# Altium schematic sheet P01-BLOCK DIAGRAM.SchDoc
size 386 x 246 mm
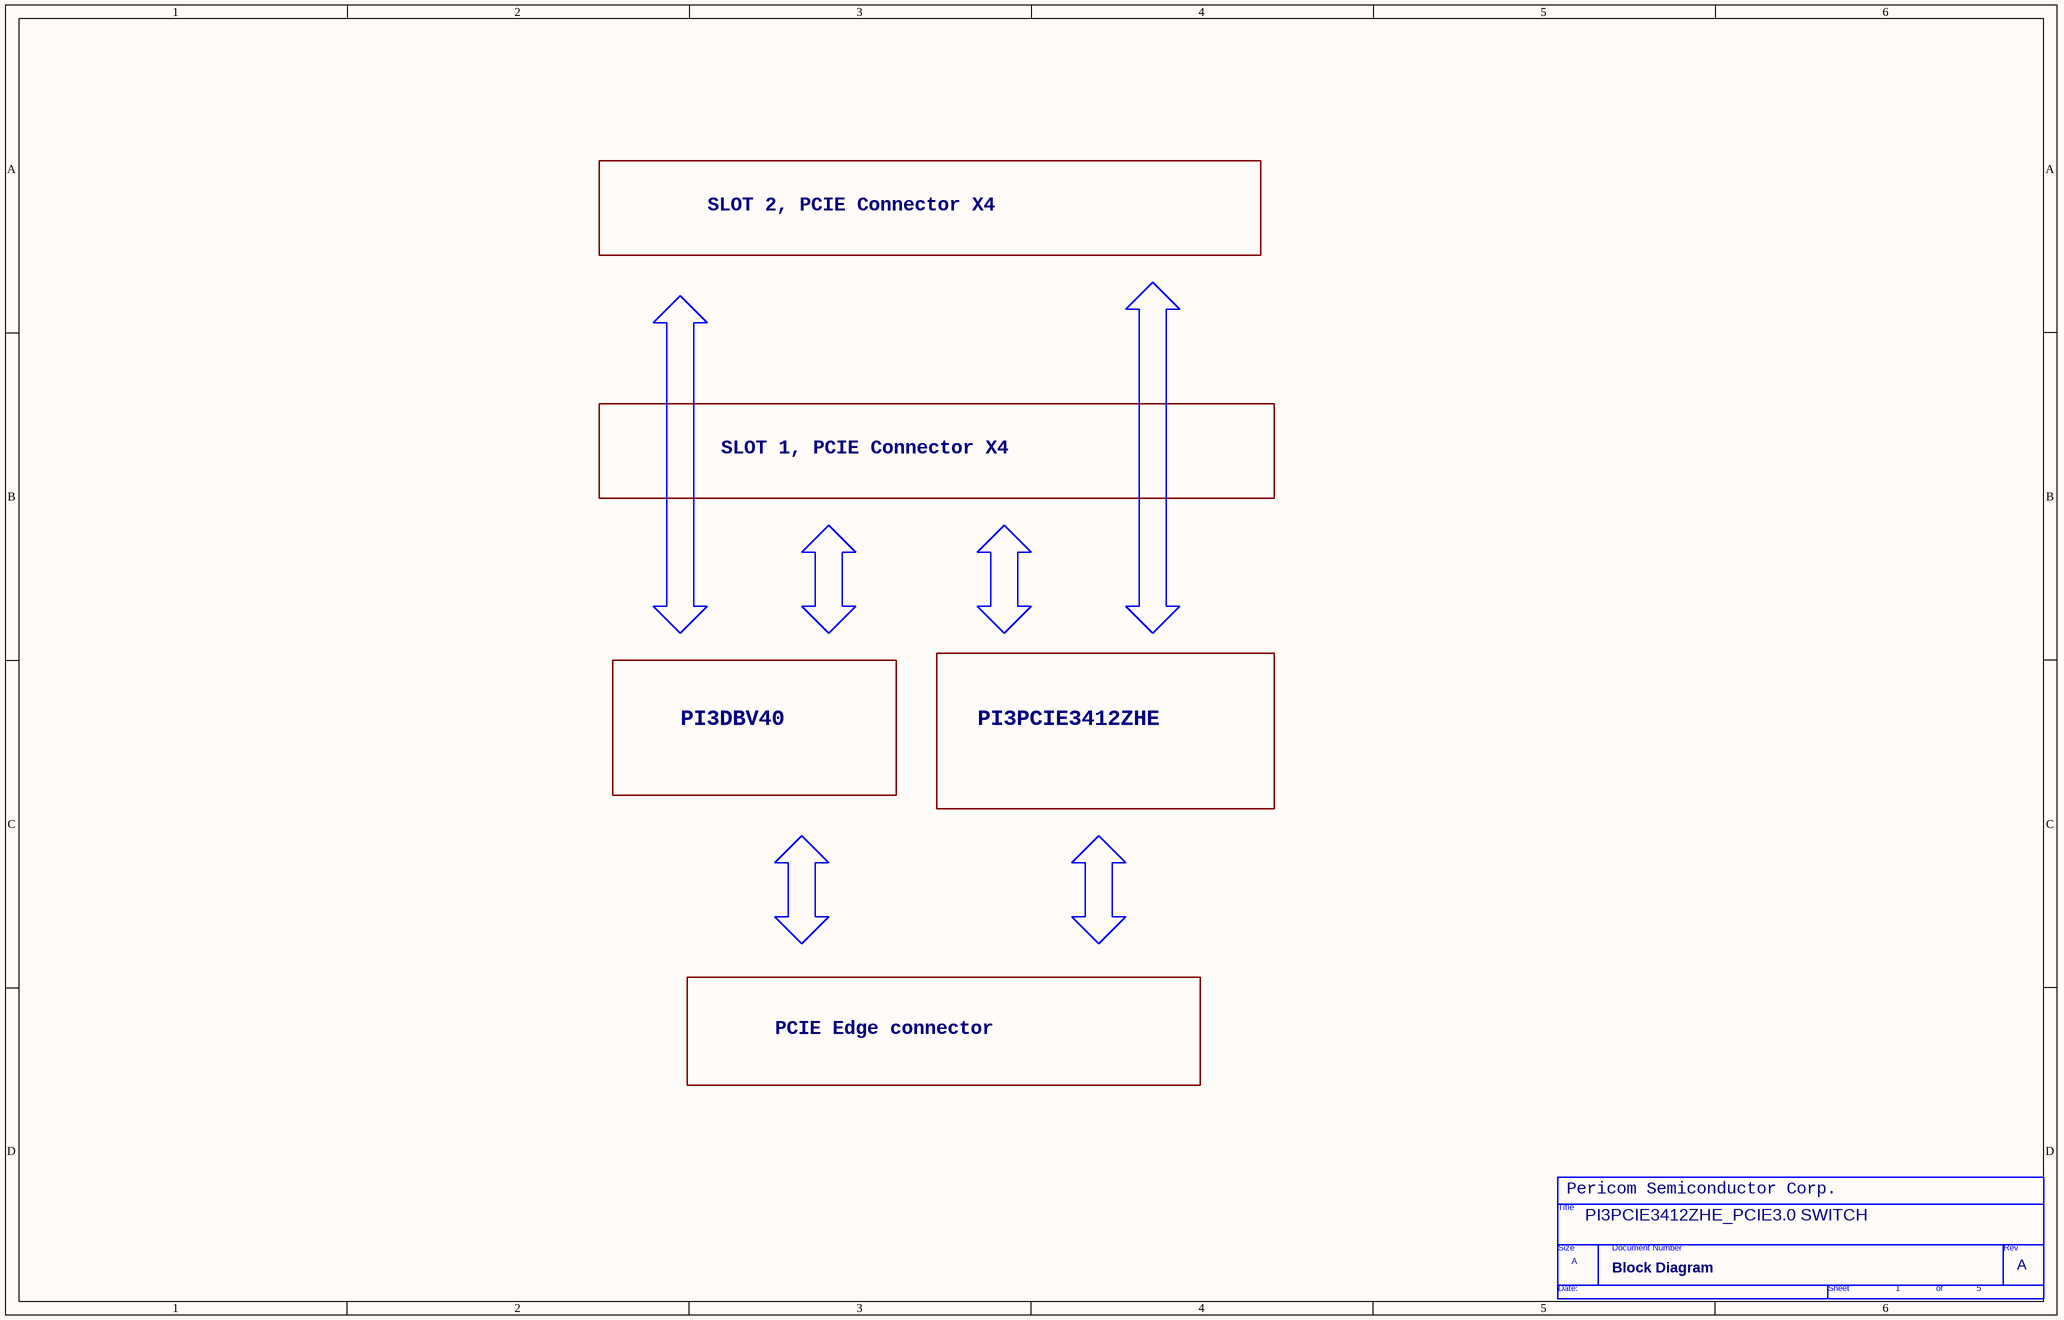
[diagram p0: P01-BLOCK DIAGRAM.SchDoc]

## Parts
*  Doc: Block Diagram  RevCode: A  Title: PI3PCIE3412ZHE_PCIE3.0 SWITCH  Page Number: 1  Page Count: 5  (hidden comment: TitleBlock0)  (graphical)

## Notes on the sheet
- SLOT 2, PCIE Connector X4
- SLOT 1, PCIE Connector X4
- PI3DBV40
- PI3PCIE3412ZHE
- PCIE Edge connector
- (near *) Pericom Semiconductor Corp.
